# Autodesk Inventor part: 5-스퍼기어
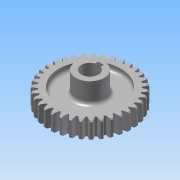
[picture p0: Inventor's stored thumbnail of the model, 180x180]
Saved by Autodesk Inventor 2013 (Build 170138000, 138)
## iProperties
Created: 2013-08
Part Number: 5-스퍼기어
Material: 강
Document SubType Name: Modeling
Designer: 한국산업디자인학원
Categories: <?xml version="1.0" encoding="UTF-16"?> <MemberInstance><Categories><FamilyTemplate><FamilyTemplateParameter ValueType="xs:double" Id="1" ObjectReferenceKey="da
Density: 1 g/cm^3
CustomPartVersion: 1
Author: 한국산업디자인학원
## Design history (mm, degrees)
sketch "Sketch1"
  geometry: C1 r 37 at (0, 0)
  constraints: 1 centre point
  dimensions: "d0" = 74 diameter of C1 (= da_da)
extrude "Extrusion1" new body sketch "Sketch1" distance "d1" = 15 (= da_b); taper "d2" = 0 deg
chamfer "모따기1" distance "d49" = 1; stored, may be unused: second distance "d50" = 2, angle "d51" = 45 deg
workplane "Work Plane2"
feature "피치 지름" dims "d4" = 10, "d5" = 0
workplane "Work Plane8"
workplane "Work Plane9"
feature "스퍼 기어" dims "da_b" = 15, "da_d" = 70, "da_aw" = 70, "da_da" = 74, "da_df" = 65, "da_dw" = 70, angle "da_beta" = 0 deg, "da_lefttooth" = 0, "da_righttooth" = 0
node "작업 평면11"
sketch "스케치3"
  geometry: C1 r 12.5 at (0, 0); C2 r 27.5 at (0, 0); 1 further point
  constraints: 2 centre point, 2 coincident
  dimensions: "d53" = 25 diameter of C1; "d55" = 55 diameter of C2
extrude "돌출2" join sketch "스케치3" distance "d56" = 31; taper "d57" = 0 deg
sketch "스케치4"
  geometry: C1 r 12.5 at (0, 0) reference; C2 r 27.5 at (0, 0); A1 r 32.5 centre (0, 0) between (9.347, 31.127) and (7.941, 31.515) reference
  constraints: 1 centre point, 1 coincident
  dimensions: "d58" = 55 diameter of C2
extrude "돌출3" cut sketch "스케치4" distance "d60" = 5; taper "d61" = 0 deg
sketch "스케치5"
  geometry: C1 r 12.5 at (0, 0) reference; C2 r 27.5 at (0, 0); A1 r 36 centre (0, 0) between (-5.215, 35.62) and (-7.633, 35.181) reference
  constraints: 1 centre point, 1 coincident
  dimensions: "d62" = 55 diameter of C2
extrude "돌출4" cut sketch "스케치5" distance "d64" = 5; taper "d65" = 0 deg
fillet "모깎기1" dims "d66" = 3
sketch "스케치6"
  geometry: L1 (-2.5, 7.071)-(-2.5, 9.8); L2 (-2.5, 9.8)-(2.5, 9.8); L3 (2.5, 9.8)-(2.5, 7.071); C1 r 12.5 at (0, 0) reference; A1 r 7.5 centre (0, 0) between (-2.5, 7.071) and (2.5, 7.071)
  constraints: 6 end point, 2 parallel, 2 point on circle, 1 centre point, 1 coincident, 1 perpendicular, 1 vertical
  dimensions: "d67" = 15 diameter of A1; "d69" = 5 distance of L1.end L2.end; "d70" = 17.3 dimension on A1 L2
extrude "돌출5" cut sketch "스케치6" stored distance "d71" = 5; taper "d72" = 0 deg
body "Solid1"
sketch "Sketch2"
  geometry: C1 r 37 at (0, 0) reference; C2 r 35 at (0, 0)
  constraints: 1 centre point, 1 coincident
  dimensions: "d3" = 70 diameter of C2 (= da_dw)
body "Srf1"
other parameters: "d17" = 0, "d34" = 0.8976 (computed from da_z), "d39" = 0, "d41" = 0, "d47" = 0, "d48" = 0, "d52" = 3
